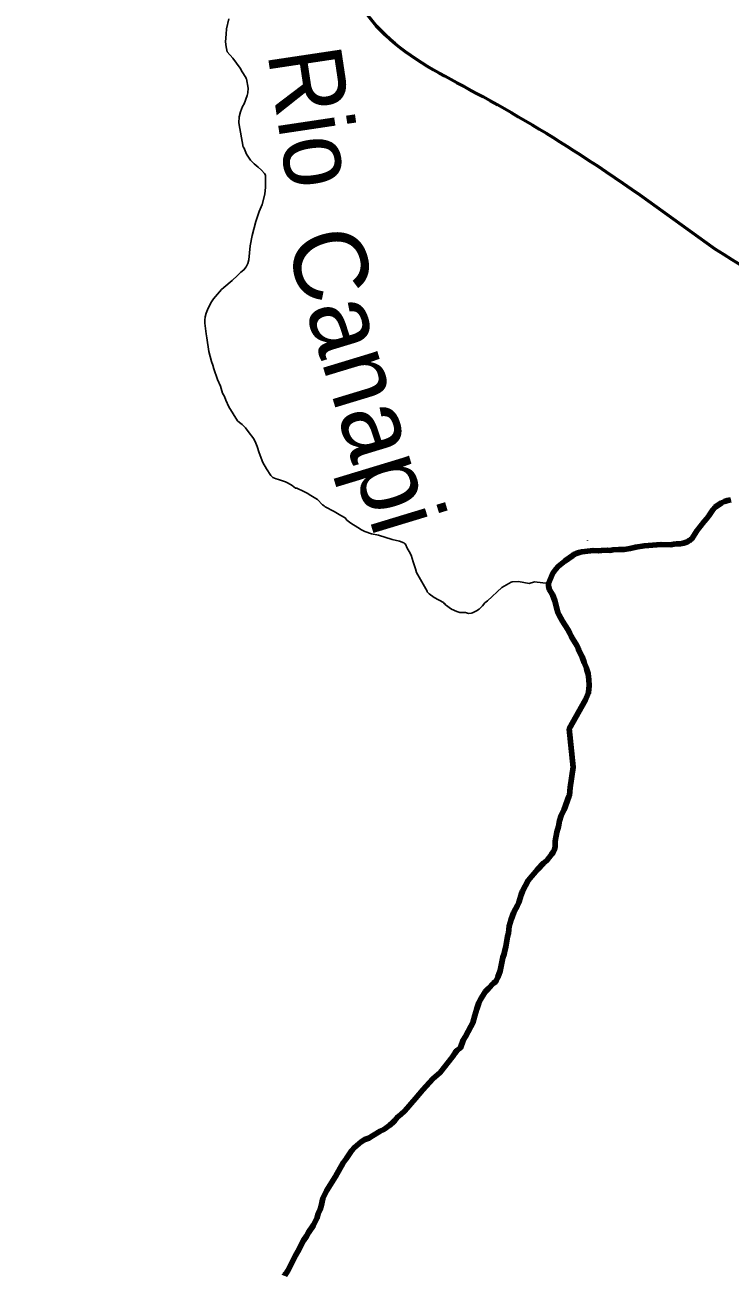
# Model space of a CAD drawing. Extents: x -1643653 to 4543381, y 1624270 to 13878484.
# Drawn here: x 651297 to 656084, y 8968437 to 8976922 of the extents above; entities that cross this region are included whole.
import ezdxf
from ezdxf.enums import TextEntityAlignment as Align

# ---------------------------------------------------------------- set-up
doc = ezdxf.new("R2010")
doc.units = 0
doc.header["$LTSCALE"] = 200
for name, color, linetype, lineweight in [('24', 7, 'Continuous', 25), ('27', 7, 'Continuous', 13), ('28', 7, 'Continuous', 53), ('60', 7, 'Continuous', 13), ('9', 7, 'Continuous', 90)]:
    doc.layers.add(name, color=color, linetype=linetype, lineweight=lineweight)
doc.layers.add('49', color=7, linetype='Continuous')

msp = doc.modelspace()

# ---------------------------------------------------------------- linework, layer by layer
at = {"layer": '24'}
for p, q in [((655116.6, 8973422.7), (655117, 8973424.3)), ((654851.3, 8973132), (654755.7, 8973142.7))]:
    msp.add_line(p, q, dxfattribs=at)
for points in [[(652799.8, 8975280.4), (652809.8, 8975302.2), (652816.1, 8975328.3), (652822.4, 8975374.6), (652826.9, 8975422.5), (652839.8, 8975493.2), (652864.5, 8975587.5), (652888.2, 8975655.6), (652908, 8975704.5), (652925.9, 8975773.4), (652929.4, 8975820.5), (652930.5, 8975902.1), (652923, 8975914.4), (652902.1, 8975937.5), (652881.4, 8975957.1), (652852.2, 8975978.9), (652827.9, 8976005.5), (652801.9, 8976045.7), (652783.3, 8976090.1), (652777.5, 8976093.8), (652748.7, 8976257.8), (652752.2, 8976297.8), (652759.6, 8976332.9), (652774.2, 8976369.2), (652784.3, 8976387.2), (652805.5, 8976443.3), (652809.5, 8976460.7), (652811.3, 8976493), (652801.1, 8976555.8), (652798.8, 8976558), (652796.5, 8976566.6), (652771.4, 8976603.6), (652757.2, 8976628.1), (652709.4, 8976696.7), (652669.3, 8976741.1), (652663.9, 8976773), (652657.8, 8976807.6), (652663.9, 8976859.5), (652664.9, 8976895.8), (652682.2, 8976964.3)], [(654755.7, 8973142.7), (654720.6, 8973132.1), (654647.5, 8973144.9), (654604.9, 8973142), (654598.8, 8973140.5), (654534.6, 8973104.9), (654437.3, 8973012.6), (654419.5, 8972998.8), (654403.8, 8972979.2), (654381.6, 8972957.8), (654363, 8972946.1), (654335.2, 8972931.4), (654326.4, 8972929.3), (654308.8, 8972928.4), (654287.9, 8972933.5), (654250.2, 8972934.8), (654229.3, 8972940.7), (654192.4, 8972956.2), (654152.5, 8972986.8), (654147.8, 8972992.5), (654142.1, 8972995.3), (654139, 8973001.3), (654076, 8973035.9), (654041.5, 8973060), (654027.3, 8973074.1), (654028.3, 8973079.5), (653955, 8973206), (653948.8, 8973231.1), (653931.5, 8973279.1), (653918, 8973324.5), (653906.3, 8973348.1), (653892.5, 8973371.7), (653880.9, 8973398.6), (653873.4, 8973402.2), (653869.2, 8973406.6), (653838.8, 8973418.7), (653790.9, 8973428.7), (653697.5, 8973459.4), (653649.6, 8973468.4), (653604, 8973484.9), (653582.4, 8973495.6), (653556.1, 8973510.9), (653509.5, 8973541.4), (653482.9, 8973561.9), (653470.5, 8973577.6), (653442.6, 8973592.3), (653395.4, 8973620.1), (653335.2, 8973650.9), (653328.8, 8973657.6), (653317.1, 8973665.3), (653282.9, 8973700.4), (653261.2, 8973715), (653237, 8973727.3), (653213.3, 8973743.3), (653191.4, 8973755.3), (653143.5, 8973777.1), (653134.4, 8973779.3), (653111.9, 8973795.2), (653085.1, 8973811.8), (653065.5, 8973821.4), (653019.2, 8973837.3), (653002.9, 8973840.6), (652981, 8973851.6), (652965.9, 8973864.6), (652937, 8973909.3), (652911.1, 8973953), (652887.5, 8974017.3), (652874.5, 8974060.1), (652864.8, 8974083.7), (652850.2, 8974112.8), (652813.3, 8974163.9), (652794.5, 8974187.8), (652771, 8974210.2), (652753.5, 8974223.6), (652741.1, 8974236.2), (652681.1, 8974329.2), (652660, 8974375.6), (652651, 8974399.9), (652639.3, 8974423.5), (652623.5, 8974469.8), (652603.2, 8974516.9), (652579.3, 8974588.4), (652572.8, 8974612), (652562.8, 8974637.3), (652546.2, 8974706.2), (652532.2, 8974799.6), (652526.8, 8974824.9), (652519.2, 8974897.6), (652518.3, 8974918.3), (652521.3, 8974941), (652527.4, 8974967.1), (652535.4, 8974989), (652558, 8975036.1), (652577.2, 8975063.9), (652631.7, 8975125.9), (652648.1, 8975141.2), (652704.5, 8975187.2), (652741, 8975221.5), (652762.8, 8975244.2), (652783.3, 8975259.7), (652799.8, 8975280.4)]]:
    msp.add_lwpolyline(points, dxfattribs=at)
at = {"layer": '24', "lineweight": 53}
for points in [[(656090.3, 8973699.3), (656067.2, 8973694.6), (656047.4, 8973688.6), (656026.8, 8973679.3), (655983.7, 8973648.4), (655968.2, 8973630.5), (655940.3, 8973590.2), (655926.4, 8973572.3), (655907.2, 8973551.6), (655857.4, 8973488), (655825.2, 8973435), (655819.5, 8973432.4), (655817.1, 8973428.1), (655813, 8973426.4), (655807.3, 8973421.2), (655797.6, 8973417.6), (655794, 8973413), (655766.8, 8973403.9), (655745.4, 8973399.7), (655722.2, 8973400.4), (655702.5, 8973398.4), (655680.3, 8973394.3), (655616.9, 8973396.2), (655501.2, 8973386.6), (655443.3, 8973378), (655404.8, 8973367.5), (655366.2, 8973362.1), (655326.8, 8973361.9), (655289.1, 8973358.7), (655269, 8973355.7), (655249.7, 8973356.6), (655212, 8973355.5), (655191.9, 8973353.5), (655154.1, 8973354.5), (655137.5, 8973353.6), (655077.8, 8973346), (655060.3, 8973342.2), (655039.3, 8973335.4), (655029.9, 8973329.2), (655023.6, 8973328.5), (655016.9, 8973321.8), (654963.5, 8973284.3), (654916.4, 8973246.2), (654900.8, 8973228.3), (654881.6, 8973201), (654851.3, 8973132), (654852.3, 8973113.8), (654858.7, 8973088.2), (654878.1, 8973056.9), (654895, 8973014.3), (654909.2, 8972953.2), (654915.3, 8972934.7), (654923.6, 8972916.2), (654947.3, 8972875.3), (654982.1, 8972819.3), (654996.2, 8972794.1), (655005.3, 8972774), (655014.6, 8972757.2), (655044.4, 8972710.5), (655053.7, 8972692), (655056.5, 8972676.5), (655080.1, 8972632.6), (655093.2, 8972594.1), (655109.8, 8972556.3), (655111.9, 8972544), (655121.8, 8972516.9), (655124, 8972498.5), (655124.2, 8972478.4), (655127.3, 8972439.8), (655123.7, 8972391.1), (655118.2, 8972380.4), (655102.9, 8972341.9), (654992.2, 8972144.1), (655019.8, 8971884.2), (654998.6, 8971745.3), (654995, 8971695.3), (654989.7, 8971685.4), (654957.7, 8971597.4), (654937.6, 8971556.5), (654925.2, 8971519.5), (654918.6, 8971481), (654907, 8971442.4), (654896.1, 8971382.9), (654895.8, 8971344.4), (654892, 8971324.4), (654883.1, 8971306.7), (654872.7, 8971291.8), (654840.1, 8971251.1), (654818.4, 8971232.1), (654818.4, 8971232.1), (654777.1, 8971189.8), (654713.1, 8971114), (654675.8, 8971041.8), (654665.8, 8971017.4), (654650.1, 8970966.2), (654641.7, 8970946), (654616.5, 8970899.6)], [(654616.5, 8970899.6), (654597.8, 8970850.8), (654585.3, 8970804.5), (654581.2, 8970781.8), (654578.8, 8970758.3), (654572.6, 8970734.7), (654560.7, 8970664), (654554.4, 8970640.4), (654550, 8970616.9), (654542.2, 8970591.6), (654533, 8970547), (654526.8, 8970523.4), (654524.2, 8970501.2), (654508.2, 8970458.4), (654499, 8970437.8), (654493.5, 8970429), (654477.7, 8970417.1), (654443, 8970382.2), (654421.1, 8970358.3), (654389.5, 8970306.2), (654379.5, 8970284), (654365, 8970242.8), (654351.1, 8970197.8), (654345.4, 8970173.5), (654336.8, 8970149.9), (654324.7, 8970123.6), (654288, 8970056.4), (654272.8, 8970031.9), (654254.6, 8969979.6), (654230.2, 8969960.2), (654218.1, 8969945.2), (654200.3, 8969917.9), (654115.1, 8969812.6), (654066, 8969768.5), (653998.5, 8969693.6), (653949.1, 8969634.7), (653875.5, 8969551.6), (653848.1, 8969526.1), (653826.1, 8969509.2), (653807.7, 8969485.9), (653788.8, 8969465.8), (653781.7, 8969461.6), (653774.9, 8969453.3), (653733.8, 8969425.9), (653708.2, 8969413.9), (653656.8, 8969380.9), (653631.1, 8969367), (653605.4, 8969356.1), (653579.7, 8969340.1), (653534.3, 8969303.2), (653514.9, 8969279.7), (653477.3, 8969225.2), (653456.6, 8969199.3), (653405, 8969106.7), (653344.1, 8969008.1), (653319.5, 8968956.7), (653307.6, 8968905.3), (653300.6, 8968881.3), (653288.5, 8968853.8), (653281.5, 8968827.4), (653256.7, 8968776), (653222.5, 8968726.1), (653207.9, 8968699.7), (653188.9, 8968672.3), (653150.5, 8968597.6), (653133.3, 8968569.4), (653084.6, 8968470), (653068.7, 8968444.2), (653061.9, 8968437.6), (653060, 8968431.6)]]:
    msp.add_lwpolyline(points, dxfattribs=at)
at = {"layer": '27'}
for points in [[(644540.6, 8982372.7), (644675.9, 8982274.9), (645321.7, 8981636.4), (645853, 8981011.1), (646805.1, 8980473.1), (647606.1, 8980240.8), (648482.7, 8979868.5), (649626.6, 8979469.5), (650871.6, 8978943), (651404, 8978495.7), (652521.8, 8977995.2), (653308.2, 8977445.1), (653712.6, 8976883.9), (654308.9, 8976487.2), (655070.4, 8976039), (655983.7, 8975399.4)], [(655983.7, 8975399.4), (656923, 8974848.7), (657608.5, 8974464.4), (658343, 8973736.5), (658963.6, 8973136.3), (659596.6, 8972485.1), (660330.5, 8971655.5), (660495.7, 8971591.2), (661115.6, 8970863.8), (661404.1, 8970086.9), (661693.8, 8969526.2), (662110.5, 8968901.3), (662312.2, 8968544.4), (662816.6, 8967664.9), (663042.2, 8967040.8), (663203.6, 8966302.6), (663365.3, 8965640.7), (663833.2, 8965053.8), (664099.5, 8964849.2), (664772, 8964426.8), (665496.3, 8964144), (666463.4, 8964000.2), (667623.1, 8964148), (668184.3, 8964285.6), (669317.4, 8964230), (670221.1, 8964150), (671187.7, 8963917.1), (671823.3, 8963711.1), (672497.1, 8963517.5), (673386.9, 8963221.4), (674492.1, 8962733.6), (675125.5, 8962146), (675556, 8961711.9), (676150.3, 8960959.1), (676174.9, 8960921)]]:
    msp.add_spline(points, degree=3, dxfattribs=at)
at = {"layer": '28'}
for points in [[(655983.7, 8975399.4), (655070.4, 8976039), (654308.9, 8976487.2), (653712.6, 8976883.9), (653308.2, 8977445.1), (652521.8, 8977995.2), (651404, 8978495.7), (650871.6, 8978943), (649626.6, 8979469.5), (648482.7, 8979868.5), (647606.1, 8980240.8), (646805.1, 8980473.1), (645853, 8981011.1), (645321.7, 8981636.4), (644675.9, 8982274.9), (644540.6, 8982372.7)], [(676174.9, 8960921), (676150.3, 8960959.1), (675556, 8961711.9), (675125.5, 8962146), (674492.1, 8962733.6), (673386.9, 8963221.4), (672497.1, 8963517.5), (671823.3, 8963711.1), (671187.7, 8963917.1), (670221.1, 8964150), (669317.4, 8964230), (668184.3, 8964285.6), (667623.1, 8964148), (666463.4, 8964000.2), (665496.3, 8964144), (664772, 8964426.8), (664099.5, 8964849.2), (663833.2, 8965053.8), (663365.3, 8965640.7), (663203.6, 8966302.6), (663042.2, 8967040.8), (662816.6, 8967664.9), (662312.2, 8968544.4), (662110.5, 8968901.3), (661693.8, 8969526.2), (661404.1, 8970086.9), (661115.6, 8970863.8), (660495.7, 8971591.2), (660330.5, 8971655.5), (659596.6, 8972485.1), (658963.6, 8973136.3), (658343, 8973736.5), (657608.5, 8974464.4), (656923, 8974848.7), (655983.7, 8975399.4)]]:
    msp.add_spline(points, degree=3, dxfattribs=at)
at = {"layer": '60', "lineweight": 25}
msp.add_spline([(814781, 9009175.5), (814787.2, 9009173.4), (814796.9, 9009173.4), (814799.4, 9009172.4), (814805.1, 9009174.5), (814805.6, 9009176.5), (814811.7, 9009179.5), (814811.7, 9009179.5), (814801.5, 9009181), (814790.7, 9009181.5), (814784.1, 9009183.1), (814777.4, 9009185.1), (814778.4, 9009175.5)], degree=3, dxfattribs=at)
at = {"layer": '9'}
for points in [[(656090.3, 8973699.3), (656067.2, 8973694.6), (656047.4, 8973688.6), (656026.8, 8973679.3), (655983.7, 8973648.4), (655968.2, 8973630.5), (655940.3, 8973590.2), (655926.4, 8973572.3), (655907.2, 8973551.6), (655857.4, 8973488), (655825.2, 8973435), (655819.5, 8973432.4), (655817.1, 8973428.1), (655813, 8973426.4), (655807.3, 8973421.2), (655797.6, 8973417.6), (655794, 8973413), (655766.8, 8973403.9), (655745.4, 8973399.7), (655722.2, 8973400.4), (655702.5, 8973398.4), (655680.3, 8973394.3), (655616.9, 8973396.2), (655501.2, 8973386.6), (655443.3, 8973378), (655404.8, 8973367.5), (655366.2, 8973362.1), (655326.8, 8973361.9), (655289.1, 8973358.7), (655269, 8973355.7), (655249.7, 8973356.6), (655212, 8973355.5), (655191.9, 8973353.5), (655154.1, 8973354.5), (655137.5, 8973353.6), (655077.8, 8973346), (655060.3, 8973342.2), (655039.3, 8973335.4), (655029.9, 8973329.2), (655023.6, 8973328.5), (655016.9, 8973321.8), (654963.5, 8973284.3), (654916.4, 8973246.2), (654900.8, 8973228.3), (654881.6, 8973201), (654851.3, 8973132), (654852.3, 8973113.8), (654858.7, 8973088.2), (654878.1, 8973056.9), (654895, 8973014.3), (654909.2, 8972953.2), (654915.3, 8972934.7), (654923.6, 8972916.2), (654947.3, 8972875.3), (654982.1, 8972819.3), (654996.2, 8972794.1), (655005.3, 8972774), (655014.6, 8972757.2), (655044.4, 8972710.5), (655053.7, 8972692), (655056.5, 8972676.5), (655080.1, 8972632.6), (655093.2, 8972594.1), (655109.8, 8972556.3), (655111.9, 8972544), (655121.8, 8972516.9), (655124, 8972498.5), (655124.2, 8972478.4), (655127.3, 8972439.8), (655123.7, 8972391.1), (655118.2, 8972380.4), (655102.9, 8972341.9), (654992.2, 8972144.1), (655019.8, 8971884.2), (654998.6, 8971745.3), (654995, 8971695.3), (654989.7, 8971685.4), (654957.7, 8971597.4), (654937.6, 8971556.5), (654925.2, 8971519.5), (654918.6, 8971481), (654907, 8971442.4), (654896.1, 8971382.9), (654895.8, 8971344.4), (654892, 8971324.4), (654883.1, 8971306.7), (654872.7, 8971291.8), (654840.1, 8971251.1), (654818.4, 8971232.1), (654818.4, 8971232.1), (654777.1, 8971189.8), (654713.1, 8971114), (654675.8, 8971041.8), (654665.8, 8971017.4), (654650.1, 8970966.2), (654641.7, 8970946), (654616.5, 8970899.6)], [(654616.5, 8970899.6), (654597.8, 8970850.8), (654585.3, 8970804.5), (654581.2, 8970781.8), (654578.8, 8970758.3), (654572.6, 8970734.7), (654560.7, 8970664), (654554.4, 8970640.4), (654550, 8970616.9), (654542.2, 8970591.6), (654533, 8970547), (654526.8, 8970523.4), (654524.2, 8970501.2), (654508.2, 8970458.4), (654499, 8970437.8), (654493.5, 8970429), (654477.7, 8970417.1), (654443, 8970382.2), (654421.1, 8970358.3), (654389.5, 8970306.2), (654379.5, 8970284), (654365, 8970242.8), (654351.1, 8970197.8), (654345.4, 8970173.5), (654336.8, 8970149.9), (654324.7, 8970123.6), (654288, 8970056.4), (654272.8, 8970031.9), (654254.6, 8969979.6), (654230.2, 8969960.2), (654218.1, 8969945.2), (654200.3, 8969917.9), (654115.1, 8969812.6), (654066, 8969768.5), (653998.5, 8969693.6), (653949.1, 8969634.7), (653875.5, 8969551.6), (653848.1, 8969526.1), (653826.1, 8969509.2), (653807.7, 8969485.9), (653788.8, 8969465.8), (653781.7, 8969461.6), (653774.9, 8969453.3), (653733.8, 8969425.9), (653708.2, 8969413.9), (653656.8, 8969380.9), (653631.1, 8969367), (653605.4, 8969356.1), (653579.7, 8969340.1), (653534.3, 8969303.2), (653514.9, 8969279.7), (653477.3, 8969225.2), (653456.6, 8969199.3), (653405, 8969106.7), (653344.1, 8969008.1), (653319.5, 8968956.7), (653307.6, 8968905.3), (653300.6, 8968881.3), (653288.5, 8968853.8), (653281.5, 8968827.4), (653256.7, 8968776), (653222.5, 8968726.1), (653207.9, 8968699.7), (653188.9, 8968672.3), (653150.5, 8968597.6), (653133.3, 8968569.4), (653084.6, 8968470), (653068.7, 8968444.2), (653061.9, 8968437.6), (653060, 8968431.6)]]:
    msp.add_lwpolyline(points, dxfattribs=at)
msp.add_spline([(637260.6, 8972975.8), (641524.5, 8971056.2), (652526.1, 8965412.7), (653164.3, 8965062.8), (670790.5, 8953770.1), (686194, 8943929.9), (696283.3, 8937647.1)], degree=3, dxfattribs=at)

# ---------------------------------------------------------------- texts
at = {"layer": '49', "width": 0.95}
msp.add_text('Rio', height=500, rotation=278.527, dxfattribs=at).set_placement((653013, 8976261.9), align=Align.CENTER)
at = {"layer": '49'}
msp.add_text('Canapi', height=500, rotation=286.879, dxfattribs=at).set_placement((653368, 8974444.7), align=Align.CENTER)

doc.saveas('drawing.dxf')
